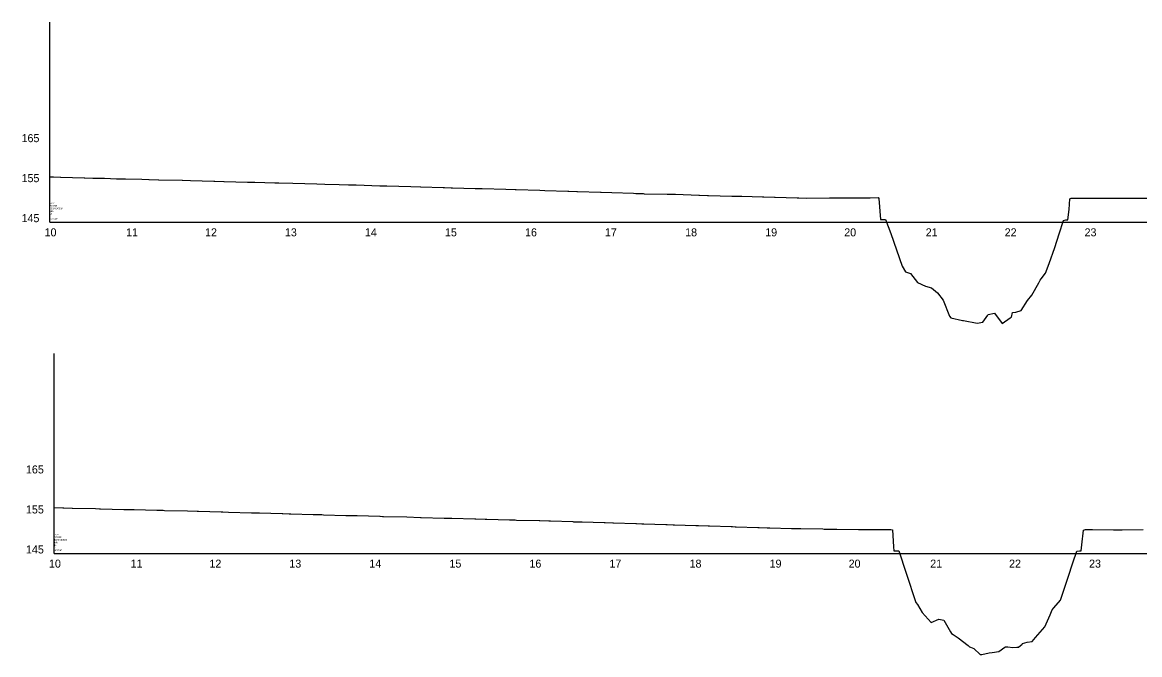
# Model space of a CAD drawing. Extents: x 573468 to 580768, y -57414 to -51768.
# Drawn here: x 573696 to 575092, y -52559 to -51768 of the extents above; entities that cross this region are included whole.
import ezdxf

# ---------------------------------------------------------------- set-up
doc = ezdxf.new("R2010")
doc.units = 0
for name, color, linetype in [('Exist Profile Cell', 7, 'Continuous'), ('Exist Vertical Profile Ground Line', 7, 'Continuous'), ('Exist Vertical Profile Horizontal Axis Label Major', 7, 'Continuous'), ('Exist Vertical Profile Vertical Axis Label', 7, 'Continuous')]:
    doc.layers.add(name, color=color, linetype=linetype)

msp = doc.modelspace()

# ---------------------------------------------------------------- linework, layer by layer
at = {"layer": 'Exist Profile Cell'}
for p, q in [((573730.1, -52018.4), (573730.1, -51768.4)), ((573730.1, -52018.4), (577107.5, -52018.4)), ((573730.1, -52018.4), (573730.1, -52018.4)), ((573735.6, -52432.5), (573735.6, -52182.5)), ((573735.6, -52432.5), (577156.7, -52432.5)), ((573735.6, -52432.5), (573735.6, -52432.5))]:
    msp.add_line(p, q, dxfattribs=at)
at = {"layer": 'Exist Vertical Profile Ground Line'}
for points in [[(573730.1, -51961.5), (573734, -51961.6), (573734.7, -51961.6), (573743.6, -51961.8), (573743.9, -51961.8), (573773.2, -51962.7), (573773.9, -51962.7), (573783.8, -51963), (573798.5, -51963.4), (573813.7, -51963.9), (573823.8, -51964.2), (573824.4, -51964.2), (573824.8, -51964.2), (573845.2, -51964.6), (573853.8, -51964.8), (573854.3, -51964.8), (573865.9, -51965.1), (573866.2, -51965.1), (573895.4, -51965.8), (573896.1, -51965.9), (573906.1, -51966.1), (573934.9, -51967), (573936.3, -51967.1), (573947.5, -51967.4), (573948, -51967.4), (573977, -51968.1), (573977.9, -51968.1), (573986.2, -51968.3), (574011.2, -51969), (574016.2, -51969.1), (574033.8, -51969.6), (574063.6, -51970.4), (574073.6, -51970.7), (574091.6, -51971.1), (574103.5, -51971.4), (574112.5, -51971.7), (574112.8, -51971.7), (574142.5, -51972.6), (574151, -51972.9), (574181, -51973.7), (574193.3, -51974), (574193.7, -51974), (574221.6, -51974.9), (574223.4, -51975), (574231.5, -51975.2), (574233, -51975.3), (574261.5, -51976), (574262.3, -51976), (574269.9, -51976.2), (574270.3, -51976.2), (574299.7, -51977.1), (574311.3, -51977.5), (574312.9, -51977.5), (574342.2, -51978.3), (574348.6, -51978.5), (574377.4, -51979.4), (574378.7, -51979.5), (574388.6, -51979.8), (574389.2, -51979.8), (574418, -51980.6), (574419.1, -51980.7), (574432.4, -51981.1), (574459.4, -51982.1), (574462.4, -51982.2), (574471.3, -51982.5), (574472.6, -51982.6), (574501.5, -51983.1), (574502.5, -51983.1), (574510.6, -51983.3), (574511.7, -51983.3), (574541.1, -51984.4), (574541.6, -51984.4), (574551.6, -51984.7), (574552.3, -51984.7), (574552.9, -51984.8), (574582.1, -51985.6), (574590.9, -51985.8), (574594.4, -51985.9), (574620.3, -51986.6), (574622.2, -51986.7), (574635.3, -51987), (574636.2, -51987), (574663.7, -51987.7), (574665.9, -51987.7), (574674.9, -51988), (574704.3, -51987.9), (574708.7, -51987.9), (574712.8, -51987.9), (574721.3, -51987.8), (574742.4, -51987.7), (574742.9, -51987.7), (574754.7, -51987.6), (574765, -51987.5), (574765.8, -51988.5), (574767.7, -52014.7), (574774.2, -52014.7), (574780.6, -52032.4), (574794.9, -52073), (574798.9, -52080.2), (574805.4, -52082.3), (574814.1, -52093.5)], [(574814.1, -52093.5), (574823.9, -52098.1), (574831.7, -52100.2), (574839.1, -52106.5), (574845.9, -52115.6), (574853.9, -52135.6), (574855.5, -52137.9), (574870.2, -52141.2), (574871.4, -52141.2), (574888.7, -52144.5), (574895.6, -52143.1), (574901.7, -52134.4), (574902.5, -52133.6), (574910.2, -52132.1), (574919.7, -52145), (574929.9, -52137.6), (574931.5, -52137), (574932.7, -52131.1), (574936.7, -52130.6), (574943.5, -52128.6), (574951.6, -52116.3), (574956.7, -52109.4), (574965.5, -52094.1), (574967.4, -52090.5), (574968.6, -52088.9), (574973.8, -52082.1), (574978.5, -52069.7), (574985.6, -52049.9), (574991.1, -52032.8), (574996.4, -52016.2), (574999.4, -52015.4), (575002, -52015.1), (575003.3, -52002.3), (575004.4, -51989), (575006.1, -51988), (575027.8, -51988.2), (575041.6, -51988.2), (575056.9, -51988.3), (575057.6, -51988.3), (575073, -51988.3), (575073.4, -51988.3), (575102.2, -51988.3)], [(573735.6, -52374.9), (573746.6, -52375.2), (573747.7, -52375.3), (573758.1, -52375.5), (573758.5, -52375.5), (573787.2, -52376.2), (573792.4, -52376.4), (573793.7, -52376.4), (573822.5, -52377.2), (573822.9, -52377.2), (573834, -52377.4), (573835.4, -52377.5), (573863.7, -52378.1), (573864.4, -52378.2), (573871.7, -52378.3), (573873.5, -52378.4), (573902.3, -52379.1), (573914.2, -52379.5), (573915.5, -52379.5), (573915.9, -52379.5), (573944.3, -52380.4), (573946.2, -52380.4), (573953.6, -52380.7), (573982.2, -52381.5), (573982.7, -52381.5), (573990.8, -52381.7), (573992.3, -52381.7), (574020.5, -52382.4), (574021.4, -52382.5), (574029.2, -52382.7), (574031.2, -52382.7), (574059.1, -52383.5), (574059.7, -52383.6), (574070.1, -52383.8), (574072.2, -52383.9), (574100.1, -52384.7), (574100.9, -52384.7), (574112.3, -52385), (574114.2, -52385), (574142.4, -52385.8), (574142.7, -52385.8), (574145.6, -52385.9), (574147.2, -52385.9), (574176.3, -52386.7), (574193.1, -52387.2), (574194.1, -52387.2), (574222.7, -52388), (574223.9, -52388.1), (574231.8, -52388.3), (574232.4, -52388.3), (574261.3, -52389.1), (574262.4, -52389.1), (574273.9, -52389.4), (574276, -52389.5), (574304.2, -52390.2), (574304.6, -52390.2), (574311.6, -52390.4), (574313, -52390.5), (574341.5, -52391.3), (574342.1, -52391.3), (574353.6, -52391.6), (574355.8, -52391.7), (574383.5, -52392.5), (574384.3, -52392.6), (574392.6, -52392.8), (574395, -52392.8), (574422.8, -52393.6), (574423.8, -52393.7), (574433.3, -52394), (574434.1, -52394), (574462.3, -52394.9), (574463.2, -52394.9), (574469.9, -52395.2), (574471, -52395.2), (574472.1, -52395.2), (574499.7, -52396.1), (574501.3, -52396.2), (574508.9, -52396.4), (574510.5, -52396.4), (574537.3, -52397.3), (574538.9, -52397.3), (574540.5, -52397.4), (574552.7, -52397.8), (574554.3, -52397.8), (574581.2, -52398.7), (574582.8, -52398.7), (574586.2, -52398.9), (574587.7, -52398.9), (574614.4, -52399.7), (574616.2, -52399.8), (574626.4, -52400.1), (574628.1, -52400.1), (574629.6, -52400.2), (574656.7, -52400.9), (574658, -52400.9), (574666.9, -52401.1), (574668.5, -52401.2), (574695.7, -52401.7), (574697.3, -52401.8), (574709.5, -52401.9), (574711.6, -52401.9)], [(574711.6, -52401.9), (574713.4, -52401.9), (574740.2, -52402.2), (574742.8, -52402.2), (574751.5, -52402.2), (574778.3, -52402.2), (574780.8, -52402.2), (574782.9, -52402.9), (574784, -52423.9), (574784.1, -52424), (574784.3, -52428.9), (574789.6, -52428.9), (574790.7, -52428.9), (574800, -52456.9), (574811.9, -52493.5), (574813.9, -52496.2), (574819.7, -52506.3), (574830.9, -52518.7), (574840.7, -52514.4), (574846.9, -52515.7), (574855.1, -52530.2), (574856.6, -52532.2), (574858.7, -52533.8), (574864.9, -52537.9), (574877.3, -52547.3), (574878.9, -52549.2), (574880.1, -52549.6), (574884.3, -52551), (574892.4, -52558.8), (574894.5, -52558.7), (574903.6, -52556.5), (574907.3, -52556.1), (574915.7, -52555), (574923.3, -52549.6), (574924.1, -52549.1), (574926.9, -52549.2), (574933.1, -52549.8), (574938.2, -52549.4), (574940.2, -52549.4), (574944.6, -52545.5), (574945, -52544.7), (574951, -52543.2), (574957.4, -52542.3), (574961.3, -52537.5), (574973.1, -52524.1), (574979.6, -52509.1), (574982.1, -52502.8), (574984.4, -52500.4), (574992.7, -52490.7), (574996, -52480.7), (575002.3, -52461.9), (575008.2, -52444), (575013.1, -52429.5), (575016.4, -52429.2), (575018.4, -52429.1), (575019.2, -52421.6), (575021.2, -52403), (575024, -52402.2), (575025.3, -52402.3), (575029.4, -52402.3), (575032.5, -52402.3), (575058.7, -52402.6), (575066, -52402.6), (575069.5, -52402.6), (575096.1, -52402.5)]]:
    msp.add_lwpolyline(points, dxfattribs=at)

# ---------------------------------------------------------------- texts
at = {"layer": 'Exist Profile Cell'}
for s, p in [('RDY', (573730.1, -51995.7)), ('PGLSB', (573730.1, -51998.9)), ('1000.000000', (573730.1, -52002.2)), ('2', (573730.1, -52011.9)), ('145', (573730.1, -52005.4)), ('10', (573730.1, -52008.7)), ('NOGAP', (573730.1, -52015.2)), ('1000.000000', (573735.6, -52416.3)), ('145', (573735.6, -52419.5)), ('RDY', (573735.6, -52409.8)), ('PGLNB', (573735.6, -52413)), ('10', (573735.6, -52422.8)), ('2', (573735.6, -52426)), ('NOGAP', (573735.6, -52429.3))]:
    msp.add_text(s, height=2, dxfattribs=at).set_placement(p)
at = {"layer": 'Exist Vertical Profile Horizontal Axis Label Major'}
for s, p in [('10', (573723.7, -52035.9)), ('11', (573825.5, -52035.9)), ('12', (573924.1, -52035.9)), ('13', (574023.9, -52035.9)), ('14', (574123.8, -52035.9)), ('15', (574223.8, -52035.9)), ('16', (574323.8, -52035.9)), ('17', (574423.6, -52035.9)), ('18', (574523.8, -52035.9)), ('19', (574623.8, -52035.9)), ('20', (574722.5, -52035.9)), ('21', (574824.3, -52035.9)), ('22', (574922.9, -52035.9)), ('23', (575022.7, -52035.9)), ('10', (573729.2, -52450)), ('11', (573831.1, -52450)), ('12', (573929.6, -52450)), ('13', (574029.4, -52450)), ('14', (574129.3, -52450)), ('15', (574229.4, -52450)), ('16', (574329.3, -52450)), ('17', (574429.2, -52450)), ('18', (574529.3, -52450)), ('19', (574629.3, -52450)), ('20', (574728, -52450)), ('21', (574829.9, -52450)), ('22', (574928.4, -52450)), ('23', (575028.3, -52450))]:
    msp.add_text(s, height=10, dxfattribs=at).set_placement(p)
at = {"layer": 'Exist Vertical Profile Vertical Axis Label'}
for s, p in [('165', (573694.9, -51918.2)), ('155', (573694.9, -51968.2)), ('145', (573694.9, -52018.2)), ('165', (573700.4, -52332.3)), ('155', (573700.4, -52382.3)), ('145', (573700.4, -52432.3))]:
    msp.add_text(s, height=10, dxfattribs=at).set_placement(p)

doc.saveas('drawing.dxf')
